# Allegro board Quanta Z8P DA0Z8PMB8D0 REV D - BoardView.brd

Outline 239.8 x 141.8 mm; copper layers: TOP, SGND, IN1, SVCC, IN2, IN3, SGND1, BOTTOM. Coordinates in mm from the lower left corner of the outline.
Outline path: 0,22.1 0.5,24.1 0.5,34.1 arc(0.79,34.81) 1.5,35.1 3,35.1 3,40.05 arc(3.15,40.4) 3.5,40.55 12.03,40.55 arc(12.43,40.15) 12.83,40.55 13.13,40.55 13.13,54.05 12.83,54.05 arc(12.43,54.45) 12.03,54.05 1,54.05 arc(0.65,54.2) 0.5,54.55 0.5,59.11 arc(0.65,59.46) 1,59.61 9.6,59.61 arc(10.09,60.01) 9.8,60.57 9.8,74.05 arc(10.09,74.61) 9.6,75.01 1,75.01 arc(0.65,75.16) 0.5,75.51 0.5,77 arc(0.65,77.35) 1,77.5 2.33,77.5 arc(2.68,77.65) 2.83,78 2.83,79.8 arc(2.68,80.15) 2.33,80.3 1,80.3 arc(0.65,80.45) 0.5,80.8 0.5,90.2 arc(0.65,90.55) 1,90.7 1.76,90.7 arc(2.11,90.85) 2.26,91.2 2.26,92.4 arc(2.11,92.75) 1.76,92.9 1.5,92.9 arc(1.15,93.05) 1,93.4 1,94.04 arc(1.15,94.39) 1.5,94.54 5.6,94.54 arc(5.74,94.48) 5.8,94.34 5.8,93.54 arc(5.86,93.4) 6,93.34 7.8,93.34 arc(7.94,93.4) 8,93.54 8,94.34 arc(8.06,94.48) 8.2,94.54 12.2,94.54 arc(12.34,94.6) 12.4,94.74 12.4,108.74 arc(12.34,108.88) 12.2,108.94 8.2,108.94 arc(8.06,109) 8,109.14 8,109.94 arc(7.94,110.08) 7.8,110.14 6,110.14 arc(5.86,110.08) 5.8,109.94 5.8,109.14 arc(5.74,109) 5.6,108.94 2,108.94 1,109.94 1,111.5 arc(1.07,111.75) 1.25,111.93 2.13,112.44 14.1,112.44 15.5,111.74 15.5,111.5 32.2,111.5 32.2,112.5 arc(32.64,113.56) 33.7,114 34.7,114 arc(35.76,113.56) 36.2,112.5 36.2,111.5 40.7,111.5 48.2,119 48.2,140.8 arc(48.49,141.51) 49.2,141.8 104.7,141.8 arc(105.41,141.51) 105.7,140.8 105.7,138.2 115.7,138.2 115.7,140.8 arc(115.99,141.51) 116.7,141.8 133.7,141.8 arc(134.41,141.51) 134.7,140.8 134.71,96.8 arc(135,96.09) 135.71,95.8 150.71,95.8 arc(151.42,95.51) 151.71,94.8 151.71,54.64 arc(152.01,53.93) 152.71,53.64 164.43,53.64 arc(165.07,53.41) 165.42,52.83 arc(169.28,48.64) 174.74,50.24 arc(177.14,51.53) 179.8,50.99 arc(179.95,50.9) 180.1,50.81 180.09,50.81 arc(180.55,50.22) 180.46,49.47 178.75,46.37 arc(182.83,44.47) 187.09,42.99 202.98,43 217.26,48.19 arc(217.64,48.18) 217.9,47.9 218.2,47.06 218.2,45.5 arc(218.35,45.15) 218.7,45 arc(219.05,44.85) 219.2,44.5 219.2,43.5 arc(219.35,43.15) 219.7,43 220.2,43 arc(220.91,43.29) 221.2,44 221.2,45.4 arc(221.05,45.75) 220.7,45.9 220.1,45.9 arc(219.75,46.05) 219.6,46.4 219.6,48 arc(219.89,48.71) 220.6,49 236.96,49 arc(237.17,48.96) 237.34,48.83 arc(237.86,48.35) 238.49,48.01 arc(238.71,47.83) 238.8,47.55 238.8,42.06 arc(238.95,41.71) 239.3,41.56 arc(239.65,41.42) 239.8,41.06 239.8,33.79 arc(239.51,33.09) 238.8,32.79 236.2,32.8 arc(235.49,32.51) 235.2,31.8 235.2,9.2 arc(234.91,8.49) 234.2,8.2 227.1,8.2 arc(226.39,8.49) 226.1,9.2 226.1,10.3 151.7,10.3 arc(150.99,10.59) 150.7,11.3 150.7,12.3 arc(150.41,13.01) 149.7,13.3 86.9,13.3 86.9,11.3 arc(86.61,10.59) 85.9,10.3 27.5,10.3 14.19,0 12.45,0 arc(11.2,2.6) 9.95,0 3.73,0 arc(3.38,0.15) 3.23,0.5 3.23,4.8 arc(3.08,5.15) 2.73,5.3 1,5.3 arc(0.65,5.45) 0.5,5.8 0.5,14.1 0,16.1 0,22.1

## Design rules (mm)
net group W5-T13B: nets EDP_RCOMP_N EDP_RCOMP_P
net group W5-TB: nets ASM_XIN ASM_XOUT
net group W10-T13B: nets INT_AMIC-VREFO MIC2-VREFO
net group W15-T13B: nets MEM_CH0_RCOMP MEM_CH1_RCOMP
net group W60-T123B: nets LCDVCC LCDVCC_R
net group DFP-S4W4.5(4: nets M_A_CLK0 M_A_CLK0# M_A_DQS0 M_A_DQS1 M_A_DQS2 M_A_DQS3 M_A_DQS4 M_A_DQS5 M_A_DQS6 M_A_DQS7 M_A_DQS#0 M_A_DQS#1 M_A_DQS#2 M_A_DQS#3 M_A_DQS#4 M_A_DQS#5 M_A_DQS#6 M_A_DQS#7 M_B_CLK0 M_B_CLK0# M_B_DQS0 M_B_DQS1 M_B_DQS2 M_B_DQS3 M_B_DQS4 M_B_DQS5 M_B_DQS6 M_B_DQS7 M_B_DQS#0 M_B_DQS#1 M_B_DQS#2 M_B_DQS#3 M_B_DQS#4 M_B_DQS#5 M_B_DQS#6 M_B_DQS#7
net group DFP-S5(4: nets CLK_PCIE_LANN CLK_PCIE_LANP CLK_PCIE_SSDN CLK_PCIE_SSDP CLK_PCIE_WLANN CLK_PCIE_WLANP EDP_AUXN EDP_AUXN_C EDP_AUXP EDP_AUXP_C EDP_TXN0 EDP_TXN0_C EDP_TXN1 EDP_TXN1_C EDP_TXN2 EDP_TXN2_C EDP_TXN3 EDP_TXN3_C EDP_TXP0 EDP_TXP0_C EDP_TXP1 EDP_TXP1_C EDP_TXP2 EDP_TXP2_C EDP_TXP3 EDP_TXP3_C INT_HDMICLK+ INT_HDMICLK+_C INT_HDMICLK+_C_RIN INT_HDMICLK+_C_ROUT INT_HDMICLK+_NOR INT_HDMICLK- INT_HDMICLK-_C INT_HDMICLK-_C_RIN INT_HDMICLK-_C_ROUT INT_HDMICLK-_NOR INT_HDMITX0N INT_HDMITX0N_C INT_HDMITX0N_C_RIN INT_HDMITX0N_C_ROUT INT_HDMITX0N_NOR INT_HDMITX0P INT_HDMITX0P_C INT_HDMITX0P_C_RIN INT_HDMITX0P_C_ROUT INT_HDMITX0P_NOR INT_HDMITX1N INT_HDMITX1N_C_RIN INT_HDMITX1N_C_ROUT INT_HDMITX1N_NOR INT_HDMITX1P INT_HDMITX1P_C_RIN INT_HDMITX1P_C_ROUT INT_HDMITX1P_NOR INT_HDMITX2N INT_HDMITX2N_C_RIN INT_HDMITX2N_C_ROUT INT_HDMITX2N_NOR INT_HDMITX2P INT_HDMITX2P_C INT_HDMITX2P_C_RIN INT_HDMITX2P_C_ROUT INT_HDMITX2P_NOR PCIE_RCOMPN PCIE_RCOMPP PCIE_RX0+_SSD PCIE_RX0-_SSD PCIE_RX1+_SSD PCIE_RX1-_SSD PCIE_RX2+_LAN PCIE_RX2+_LAN_C PCIE_RX2-_LAN PCIE_RX2-_LAN_C PCIE_RX3+_WLAN PCIE_RX3-_WLAN PCIE_TX0+_SSD PCIE_TX0-_SSD PCIE_TX1+_SSD PCIE_TX1-_SSD PCIE_TX2+ PCIE_TX2+_LAN PCIE_TX2- PCIE_TX2-_LAN PCIE_TX3+ PCIE_TX3+_WLAN PCIE_TX3- PCIE_TX3-_WLAN SATA_RXN0 SATA_RXN0_C SATA_RXN0_CN SATA_RXN0_M2 SATA_RXN0_RD SATA_RXN1 SATA_RXN1_R SATA_RXP0 SATA_RXP0_C SATA_RXP0_CN SATA_RXP0_M2 SATA_RXP0_RD SATA_RXP1 SATA_RXP1_R SATA_TXN0 SATA_TXN0_C SATA_TXN0_CN SATA_TXN0_M2 SATA_TXN0_RD SATA_TXN1 SATA_TXN1_C SATA_TXP0 SATA_TXP0_C SATA_TXP0_CN SATA_TXP0_M2 SATA_TXP0_RD SATA_TXP1 SATA_TXP1_C USB3_0_RXN USB3_0_RXN_R USB3_0_RXP USB3_0_RXP_R USB3_0_TXN USB3_0_TXN_C USB3_0_TXN_R USB3_0_TXP USB3_0_TXP_C USB3_0_TXP_R USB3_1_RXN USB3_1_RXP USB3_1_TXN USB3_1_TXN_CN USB3_1_TXP USB3_1_TXP_CN USB3_2_RXN USB3_2_RXP USB3_2_TXN USB3_2_TXN_CN USB3_2_TXP USB3_2_TXP_CN USBP0+ USBP0+_R USBP0- USBP0-_R USBP1+ USBP1- USBP2+ USBP2+_R USBP2- USBP2-_R USBP3+ USBP3+_R USBP3- USBP3-_R USBP4+ USBP4- USBP5+ USBP5- USBP6+ USBP6- USBP7+ USBP7-
net group DFP-S5W5-B: nets PCIE_RX1+_SSD_R PCIE_RX1-_SSD_R PCIE_TX1+_SSD_C PCIE_TX1-_SSD_C
net group DFP-S6.5(7)W5(4: nets ODD_RXN ODD_RXN_C ODD_RXP ODD_RXP_C ODD_TXN ODD_TXN_C ODD_TXP ODD_TXP_C
net group DFP-S20W5(4: nets LAN_MX0+ LAN_MX0- LAN_MX1+ LAN_MX1- LAN_MX2+ LAN_MX2- LAN_MX3+ LAN_MX3- MDI_0+ MDI_0- MDI_1+ MDI_1- MDI_2+ MDI_2- MDI_3+ MDI_3-
net group W5(4: nets 2ND_MBCLK 2ND_MBDATA AZ_CODEC_BITCLK AZ_CODEC_RST# AZ_CODEC_SDIN0 AZ_CODEC_SDOUT AZ_CODEC_SYNC AZ_SDIN0_R CLK_LAN_REQ# CLK_PCI_EC CLK_PCIE_LAN_REQ# CLK_PCIE_SSD_REQ# CLK_SCLK CLK_SDATA CLKDRV_RCOMP CLKREQ_SSD# DDCCLK_NOR DDCCLK_NOR-1 DDCCLK_RIN DDCCLK_ROUT DDCDATA_NOR DDCDATA_NOR-1 DDCDATA_RIN DDCDATA_ROUT DDI0_RCOMP_N DDI0_RCOMP_P DMIC_CLK DMIC_DAT EMMC_CLK EMMC_CMD EMMC_DATA_0 EMMC_DATA_1 EMMC_DATA_2 EMMC_DATA_3 EMMC_DATA_4 EMMC_DATA_5 EMMC_DATA_6 EMMC_DATA_7 EMMC_RCLK FAN_PWM H_CPU_SVIDCLK H_CPU_SVIDDAT HDA_BCLK_R HDA_RST#_R HDA_SDO_R HDA_SYNC_R HDMI_DDCCLK HDMI_DDCCLK_SW HDMI_DDCDATA HDMI_DDCDATA_SW HDMI_HPD HDMI_HPD_NOR HDMI_HPD_NOR-1 HDMI_HPD_RIN HDMI_HPD_RIN_Q HDMI_HPD_ROUT I2C4_SCL I2C4_SCL_C I2C4_SDA I2C4_SDA_C INT_HDMI_HPD# LPC_CLKOUT0 LPC_CLKOUT1 M_A_DQ0 M_A_DQ1 M_A_DQ2 M_A_DQ3 M_A_DQ4 M_A_DQ5 M_A_DQ6 M_A_DQ7 M_A_DQ8 M_A_DQ9 M_A_DQ10 M_A_DQ11 M_A_DQ12 M_A_DQ13 M_A_DQ14 M_A_DQ15 M_A_DQ16 M_A_DQ17 M_A_DQ18 M_A_DQ19 M_A_DQ20 M_A_DQ21 M_A_DQ22 M_A_DQ23 M_A_DQ24 M_A_DQ25 M_A_DQ26 M_A_DQ27 M_A_DQ28 M_A_DQ29 M_A_DQ30 M_A_DQ31 M_A_DQ32 M_A_DQ33 M_A_DQ34 M_A_DQ35 M_A_DQ36 M_A_DQ37 M_A_DQ38 M_A_DQ39 M_A_DQ40 M_A_DQ41 M_A_DQ42 M_A_DQ43 M_A_DQ44 M_A_DQ45 M_A_DQ46 M_A_DQ47 M_A_DQ48 M_A_DQ49 M_A_DQ50 M_A_DQ51 M_A_DQ52 M_A_DQ53 M_A_DQ54 M_A_DQ55 M_A_DQ56 M_A_DQ57 M_A_DQ58 M_A_DQ59 M_A_DQ60 M_A_DQ61 M_A_DQ62 M_A_DQ63 M_B_DQ0 M_B_DQ1 M_B_DQ2 M_B_DQ3 M_B_DQ4 M_B_DQ5 M_B_DQ6 M_B_DQ7 M_B_DQ8 M_B_DQ9 M_B_DQ10 M_B_DQ11 M_B_DQ12 M_B_DQ13 M_B_DQ14 M_B_DQ15 M_B_DQ16 M_B_DQ17 M_B_DQ18 M_B_DQ19 M_B_DQ20 M_B_DQ21 M_B_DQ22 M_B_DQ23 M_B_DQ24 M_B_DQ25 M_B_DQ26 M_B_DQ27 M_B_DQ28 M_B_DQ29 M_B_DQ30 M_B_DQ31 M_B_DQ32 M_B_DQ33 M_B_DQ34 M_B_DQ35 M_B_DQ36 M_B_DQ37 M_B_DQ38 M_B_DQ39 M_B_DQ40 M_B_DQ41 M_B_DQ42 M_B_DQ43 M_B_DQ44 M_B_DQ45 M_B_DQ46 M_B_DQ47 M_B_DQ48 M_B_DQ49 M_B_DQ50 M_B_DQ51 M_B_DQ52 M_B_DQ53 M_B_DQ54 M_B_DQ55 M_B_DQ56 M_B_DQ57 M_B_DQ58 M_B_DQ59 M_B_DQ60 M_B_DQ61 M_B_DQ62 M_B_DQ63 MA_DRAMRST# MB_DRAMRST# MBCLK MBDATA MCSI_DPHY1.1_RCOMP MCSI_DPHY1.2_RCOMP MDSI_RCOMP N22234733 PCH_MBCLK0_R PCH_MBDAT0_R PCH_SPI_CLK PCH_SPI_CS0# PCH_SPI_IO2 PCH_SPI_IO3 PCH_SPI_SI PCH_SPI_SO PCIE_CLKREQ_WLAN# PCLK_TPM PMU_RCOMP RSMRST# RTC_RST# RTC_TEST# RTC_X1 RTC_X2 SD_CLK_R SP1=SD_D1 SP2=SD_D0=MS_D1 SP3=SD_CLK=MS_D0 SP4=SD_CMD=MS_D2 SP5=SD_D3=MS_D3 SP6=SD_D2=MS_CLK SP7=SD_WP=MS_BS SP8=SD_CD# SPI_CLK SPI_CS0 SPI_DI SPI_DO TPCLK TPDATA USB_SSIC_RCOMP USBCOMP VCCGI_SENSE VCCGISS_SENSE VR_SVID_ALERT#_VCORE XTAL192_IN XTAL192_OUT
net group W5(4: nets CLK_PCI_LPC CLKRUN# CLKRUN#_R LPC_LAD0 LPC_LAD0_R LPC_LAD1 LPC_LAD1_R LPC_LAD2 LPC_LAD2_R LPC_LAD3 LPC_LAD3_R LPC_LFRAME# LPC_LFRAME#_R SOC_SERIRQ SOC_SERIRQ_R
net group W6(5: nets M_A_A0 M_A_A1 M_A_A2 M_A_A3 M_A_A4 M_A_A5 M_A_A6 M_A_A7 M_A_A8 M_A_A9 M_A_A10 M_A_A11 M_A_A12 M_A_A13 M_A_A14 M_A_A15 M_A_BS#0 M_A_BS#1 M_A_BS#2 M_A_CAS# M_A_CKE0 M_A_CS#0 M_A_ODT0 M_A_RAS# M_A_WE# M_B_A0 M_B_A1 M_B_A2 M_B_A3 M_B_A4 M_B_A5 M_B_A6 M_B_A7 M_B_A8 M_B_A9 M_B_A10 M_B_A11 M_B_A12 M_B_A13 M_B_A14 M_B_A15 M_B_BS#0 M_B_BS#1 M_B_BS#2 M_B_CAS# M_B_CKE0 M_B_CS#0 M_B_ODT0 M_B_RAS# M_B_WE#
net group W10-T123B: nets +3V_LDO_EC RSET VDD33/18
net group W12-T123B: nets +3V_EC +3VPCU_EC +3VPCU_ECPLL +A3VPCU VSTBY_FSPI
net group W15-T123B: nets +SMDDR_VREF_CA_A +SMDDR_VREF_CA_B +SMDDR_VREF_DQ_A +SMDDR_VREF_DQ_B
net group W20-T13B: nets EMMC_RCOMP GPIO_RCOMP HP-L2 HP-L3 HP-R2 HP-R3 LINE1-L LINE1-R LINE1-VREFO-L LINE1-VREFO-R
net group W20-T123B: nets 1.8V_LDO +1.2V_ASM +1.05V +1.5V +1.5VA +1.8V +1.8V_EMMC +1.8V_S5 +1.24V_S5 +1.35VSUS +3V +3V_ASM +3V_EMMC +3V_M2 +3V_RTC +3V_RTC_1 +3V_S5 +3VPCU +5V +5V_ODD +5V_S5 +5VA +5VPCU +VCC_1.05V_INT +VCC_1.05V_IO +VCC_1.8V +VCC_1.24V_AUD_ISH_PLL +VCC_1.24V_DSI_CSI +VCC_1.24V_GLM +VCC_1.24V_MPHY +VCC_1.24V_USB2 +VCC_3.3V +VDDI_EMMC +VDDQ CODEC_VREF DUALDMIC_PWR HDMI_5V VCCRTC_2
net group W30-T123B: nets +5V_FAN1 LAN_MCT0 LAN_MCT1 LAN_MCT2 LAN_MCT3 TERM9
net group W40-T13B: nets L_SPK+ L_SPK- R_SPK+ R_SPK- RING2 SLEEVE
net group W40-T123B: nets +5V_PVDD +AZA_VDD +VDDQ_VTT +WL_VDD LANVCC REGOUT VCC_XD VDD10 VOUT_BACKLIGHT
net group W50-T123B: nets +TPVDD
net group W80-T123B: nets +TYPEC_VBUS HDD+M2_PWR USBPWR1 USBPWR2

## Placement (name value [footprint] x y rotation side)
C1  180p/50V_4  [C0402]  62.6 132.29 270 top
C2  0.1u/25V_4  [C0402]  60.59 129.42 270 top
C3  330u/2V_7343H1.9  [CC7343]  95.74 123.65 90 top
C4  47u/6.3V_8  [C0805]  107.56 119.46 0 top
C5  0.1u/16V_4  [C0402]  72.28 118.29 180 top
C6  22u/6.3V_6  [C0603]  107.43 117.56 0 top
C7  22u/6.3V_6  [C0603]  88.51 117.43 180 top
C8  22u/6.3V_6  [C0603]  107.43 115.91 0 top
C9  100p/50V_4  [C0402]  52.18 109.43 90 top
C10  0.01u/50V_4  [C0402]  37.09 100.63 0 top
C11  1u/6.3V_4  [C0402]  88.47 97.59 270 top
C12  1u/6.3V_4  [C0402]  81.94 96.99 270 top
C13  1u/6.3V_4  [C0402]  91.36 96.87 270 top
C14  1u/6.3V_4  [C0402]  83.82 96.27 270 top
C15  1u/6.3V_4  [C0402]  90.25 95.77 90 top
C16  1u/6.3V_4  [C0402]  84.44 94.52 90 top
C17  1u/6.3V_4  [C0402]  97.54 94 180 top
C19  1u/6.3V_4  [C0402]  95.24 93.74 270 top
C20  1u/6.3V_4  [C0402]  96.2 93.74 270 top
C21  1u/6.3V_4  [C0402]  97.54 93.04 180 top
C23  1u/6.3V_4  [C0402]  82.77 92.79 270 top
C24  1u/6.3V_4  [C0402]  83.79 92.79 270 top
C25  1u/6.3V_4  [C0402]  93.3 92.58 270 top
C26  1u/6.3V_4  [C0402]  94.26 92.58 270 top
C27  1u/6.3V_4  [C0402]  89.24 91.62 0 top
C28  TPC@0.1u/16V_4  [C0402]  13.85 91.6 0 top
C29  1u/6.3V_4  [C0402]  82.46 91.45 0 top
C30  1u/6.3V_4  [C0402]  96 91.36 270 top
C31  1u/6.3V_4  [C0402]  91.03 91.2 270 top
C32  22u/6.3V_6  [C0603]  94.16 90.86 180 top
C33  22u/6.3V_6  [C0603]  87.01 90.79 180 top
C34  15p/50V_4  [C0402]  67.93 90.66 90 top
C35  22u/6.3V_6  [C0603]  97.91 90.65 0 top
C36  TPC@0.1u/16V_4  [C0402]  13.85 90.58 0 top
C37  1u/6.3V_4  [C0402]  84.26 90.5 270 top
C38  1u/6.3V_4  [C0402]  85.22 90.5 270 top
C39  1u/6.3V_4  [C0402]  82.44 90.48 0 top
C40  22u/6.3V_6  [C0603]  119.58 90.34 270 top
C41  22u/6.3V_6  [C0603]  89.04 89.83 270 top
C42  TPC@10u/6.3V_4  [C0402_2]  22.13 89.27 270 top
C43  TPC@1000p/50V_4  [C0402]  23.32 89.27 270 top
C44  1u/6.3V_4  [C0402]  97.06 89.08 180 top
C45  1u/6.3V_4  [C0402]  83.26 89.04 180 top
C46  22u/6.3V_6  [C0603]  92.13 88.96 270 top
C47  15p/50V_4  [C0402]  67.93 88.88 270 top
C48  1u/6.3V_4  [C0402]  86.12 88.67 180 top
C49  1u/6.3V_4  [C0402]  95.11 88.55 0 top
C50  0.1u/16V_4  [C0402]  76.45 88.51 0 top
C51  TPC@0.1u/16V_4  [C0402]  14.06 88.33 0 top
C52  TPC@10u/6.3V_4  [C0402_2]  31.48 88.09 270 top
C53  TPC@10u/6.3V_4  [C0402_2]  32.88 88.09 270 top
C54  TPC@100p/50V_4  [C0402]  24.6 88.02 270 top
C55  TPC@0.1u/16V_4  [C0402]  14.06 87.31 0 top
C56  1u/6.3V_4  [C0402]  93.7 87.3 0 top
C57  *1u/6.3V_4  [C0402]  95.99 87.23 0 top
C58  0.1u/16V_4  [C0402]  71.61 87.08 0 top
C59  1u/6.3V_4  [C0402]  81.14 86.97 90 top
C60  *1u/6.3V_4  [C0402]  97.35 86.87 90 top
C61  1u/6.3V_4  [C0402]  82.11 86.74 90 top
C62  1u/6.3V_4  [C0402]  83.07 86.74 90 top
C63  1u/6.3V_4  [C0402]  84.03 86.74 90 top
C64  22u/6.3V_6  [C0603]  85.22 86.41 90 top
C65  22u/6.3V_6  [C0603]  86.63 86.41 90 top
C66  22u/6.3V_6  [C0603]  92.13 86.34 270 top
C67  1u/6.3V_4  [C0402]  96.01 86.27 180 top
C68  22u/6.3V_6  [C0603]  123.69 86.25 270 top
C69  *22u/6.3V_6  [C0603]  125.12 86.25 270 top
C70  0.1u/16V_4  [C0402]  76.08 86.1 90 top
C71  1u/6.3V_4  [C0402]  93.63 85.96 90 top
C72  1u/6.3V_4  [C0402]  94.65 85.96 270 top
C73  1u/6.3V_4  [C0402]  88.59 85.85 180 top
C74  1u/6.3V_4  [C0402]  96.28 85.08 180 top
C75  TPC@0.1u/25V_4  [C0402]  13.96 85.81 180 top
C76  1u/6.3V_4  [C0402]  88.59 84.89 180 top
C77  1u/6.3V_4  [C0402]  93.25 84.32 180 top
C78  1u/6.3V_4  [C0402]  87.25 84.2 90 top
C79  0.1u/16V_4  [C0402]  77.14 84.03 0 top
C80  1u/6.3V_4  [C0402]  94.63 83.78 90 top
C81  22u/6.3V_6  [C0603]  90.97 83.58 270 top
C82  1u/6.3V_4  [C0402]  89.65 83.55 90 top
C83  1u/6.3V_4  [C0402]  95.99 83.55 180 top
C84  22u/6.3V_6  [C0603]  97.85 83.53 90 top
C85  22u/6.3V_6  [C0603]  85.11 83.46 0 top
C86  1u/6.3V_4  [C0402]  92.55 83.36 180 top
C87  22u/6.3V_6  [C0603]  82.48 83.02 180 top
C88  22u/6.3V_6  [C0603]  99.87 82.89 0 top
C89  22u/6.3V_6  [C0603]  87.86 82.63 0 top
C90  1u/6.3V_4  [C0402]  93.93 82.36 180 top
C91  22u/6.3V_6  [C0603]  65.75 82.34 270 top
C92  22u/6.3V_6  [C0603]  63.48 82.32 180 top
C93  1u/6.3V_4  [C0402]  92.22 81.51 90 top
C94  22u/6.3V_6  [C0603]  99.16 81.27 0 top
C95  22u/6.3V_6  [C0603]  82.47 80.35 180 top
C96  1u/6.3V_4  [C0402]  94.15 79.19 0 top
C97  0.1u/16V_4  [C0402]  90.25 78.72 90 top
C98  22u/6.3V_6  [C0603]  85.99 78.35 0 top
C99  22u/6.3V_6  [C0603]  94.98 77.61 180 top
C100  22u/6.3V_6  [C0603]  99.88 76.79 0 top
C101  0.1u/16V_4  [C0402]  91.66 76.25 180 top
C102  0.1u/16V_4  [C0402]  88.59 75.69 90 top
C103  0.1u/16V_4  [C0402]  89.93 75.66 180 top
C104  1u/6.3V_4  [C0402]  101.68 75.59 180 top
C105  *0.1u/16V_4  [C0402]  31.6 72.41 180 top
C106  *0.1u/16V_4  [C0402]  31.6 71.4 180 top
C107  *0.1u/16V_4  [C0402]  34.88 70.38 0 top
C108  0.1u/16V_4  [C0402]  37.25 70.38 180 top
C109  *0.1u/16V_4  [C0402]  25.54 70.18 270 top
C110  *0.1u/16V_4  [C0402]  34.88 69.42 0 top
C111  0.1u/16V_4  [C0402]  37.25 69.42 180 top
C112  *0.1u/16V_4  [C0402]  34.88 67.32 0 top
C113  0.1u/16V_4  [C0402]  37.25 67.32 180 top
C114  *0.1u/16V_4  [C0402]  34.88 66.36 0 top
C115  0.1u/16V_4  [C0402]  37.25 66.36 180 top
C116  *0.1u/16V_4  [C0402]  34.88 64.26 0 top
C117  0.1u/16V_4  [C0402]  37.25 64.26 180 top
C118  *0.1u/16V_4  [C0402]  34.88 63.3 0 top
C119  0.1u/16V_4  [C0402]  37.25 63.3 180 top
C120  10u/6.3V_4  [C0402]  54.29 62.03 90 top
C121  1u/6.3V_4  [C0402]  55.36 62.03 270 top
C122  *0.1u/16V_4  [C0402]  34.88 61.19 0 top
C123  0.1u/16V_4  [C0402]  37.25 61.19 180 top
C124  *0.1u/16V_4  [C0402]  34.88 60.23 0 top
C125  0.1u/16V_4  [C0402]  37.25 60.23 180 top
C126  *0.1u/16V_4  [C0402]  27.42 59.77 270 top
C127  *0.1u/16V_4  [C0402]  28.56 59.77 270 top
C128  *0.1u/16V_4  [C0402]  15.48 58.88 180 top
C129  *0.1u/16V_4  [C0402]  30.32 58.83 270 top
C130  *0.1u/16V_4  [C0402]  31.28 58.83 270 top
C131  *0.1u/16V_4  [C0402]  32.24 58.83 270 top
C132  10u/6.3V_4  [C0402]  85.84 58.83 270 top
C133  10u/6.3V_4  [C0402]  64.91 58.53 270 top
C134  10u/6.3V_4  [C0402]  65.92 58.53 270 top
C135  1u/6.3V_4  [C0402]  23.74 58.23 0 top
C136  1u/6.3V_4  [C0402]  118.05 58.2 270 top
C137  *0.1u/16V_4  [C0402]  15.48 57.87 180 top
C138  4.7u/6.3V_4  [C0402_2]  12.77 57.75 270 top
C139  470p/50V_4  [C0402]  47.87 57.61 180 top
C140  470p/50V_4  [C0402]  50.41 57.61 180 top
C141  0.1u/16V_4  [C0402]  47.87 56.6 0 top
C142  0.1u/16V_4  [C0402]  50.41 56.6 0 top
C143  1u/6.3V_4  [C0402]  85.84 56.55 270 top
C144  0.1u/16V_4  [C0402]  20.07 55.62 90 top
C145  470p/50V_4  [C0402]  21.03 55.62 90 top
C146  2.2u/10V_4  [C0402]  47.87 55.58 0 top
C147  2.2u/10V_4  [C0402]  50.41 55.58 0 top
C148  1u/6.3V_4  [C0402]  68.58 55.02 90 top
C149  470p/50V_4  [C0402]  118.35 54.56 0 top
C150  10u/6.3V_4  [C0402]  103.16 54.33 270 top
C151  10u/6.3V_4  [C0402]  100.95 54.17 0 top
C152  0.1u/16V_4  [C0402]  118.35 53.55 180 top
C153  1u/6.3V_4  [C0402]  68.58 53.16 270 top
C154  0.1u/16V_4  [C0402]  25.2 52.91 0 top
C155  *1.6p/50V_4  [C0402]  20.55 52.79 0 top
C156  2.2u/10V_4  [C0402]  118.35 52.53 180 top
C157  1u/6.3V_4  [C0402]  82.66 52.41 90 top
C158  10u/6.3V_4  [C0402]  85.84 52.41 270 top
C159  0.1u/16V_4  [C0402]  25.2 51.95 0 top
C160  10u/6.3V_4  [C0402]  50.66 51.67 90 top
C161  *1.6p/50V_4  [C0402]  20.55 51.52 0 top
C162  10u/6.3V_4  [C0402]  50.61 49.61 270 top
C163  2.2u/10V_4  [C0402]  118.35 49.23 180 top
C164  10u/6.3V_4  [C0402]  85.41 48.8 180 top
C165  0.1u/16V_4  [C0402]  118.35 48.21 180 top
C166  1u/6.3V_4  [C0402]  82.82 47.88 270 top
C167  470p/50V_4  [C0402]  118.35 47.2 0 top
C168  1u/6.3V_4  [C0402]  82.82 45.93 90 top
C169  *1.6p/50V_4  [C0402]  30.6 45.5 0 top
C170  *1.6p/50V_4  [C0402]  30.61 44.3 0 top
C171  1u/6.3V_4  [C0402]  118.35 44.07 180 top
C172  10u/6.3V_4  [C0402_2]  159.75 43.39 0 top
C173  0.1u/16V_4  [C0402]  159.75 42.25 180 top
C174  0.1u/16V_4  [C0402]  159.75 41.23 180 top
C175  1u/6.3V_4  [C0402]  118.38 42.98 180 top
C176  0.1u/16V_4  [C0402]  23.4 40.99 90 top
C177  0.1u/16V_4  [C0402]  25.32 41.24 90 top
C178  0.1u/16V_4  [C0402]  33.56 40.8 90 top
C179  10p/50V_4  [C0402]  26.96 40.62 180 top
C180  10p/50V_4  [C0402]  28.87 40.62 0 top
C181  EJ@0.01u/50V_4  [C0402]  209.73 40.14 180 top
C182  0.1u/16V_4  [C0402]  201.4 40.08 180 top
C183  0.01u/50V_4  [C0402]  201.4 39.06 180 top
C184  EJ@0.01u/50V_4  [C0402]  209.73 38.61 180 top
C185  0.01u/50V_4  [C0402]  201.42 38.05 180 top
C186  0.1u/16V_4  [C0402]  34.61 38.04 90 top
C187  *0.1u/16V_4  [C0402]  35.57 38.04 90 top
C188  10u/6.3V_4  [C0402_2]  36.64 38.04 270 top
C189  0.1u/16V_4  [C0402]  22.7 37.45 180 top
C190  TPM@10u/6.3V_4  [C0402_2]  153.02 37.26 180 top
C191  EJ@0.01u/50V_4  [C0402]  209.73 37.08 180 top
C192  CB@0.01u/50V_4  [C0402]  210.52 37.08 0 top
C193  0.01u/50V_4  [C0402]  201.42 37.03 180 top
C194  180p/50V_4  [C0402]  145.53 36.66 270 top
C195  180p/50V_4  [C0402]  135.68 36.18 0 top
C196  TPM@0.1u/16V_4  [C0402]  153.02 36.12 180 top
C197  0.01u/50V_4  [C0402]  201.42 35.93 180 top
C198  CB@0.01u/50V_4  [C0402]  210.56 35.62 0 top
C199  EJ@0.01u/50V_4  [C0402]  209.76 35.62 180 top
C200  4.7u/6.3V_4  [C0402_2]  33.83 35.18 90 top
C201  TPM@0.1u/16V_4  [C0402]  163 35.06 180 top
C202  0.1u/16V_4  [C0402]  35.12 34.89 270 top
C203  0.1u/16V_4  [C0402]  36.08 34.89 270 top
C204  *0.1u/16V_4  [C0402]  37.04 34.89 270 top
C205  0.1u/16V_4  [C0402]  138.26 34.75 270 top
C206  0.1u/16V_4  [C0402]  142.46 34.75 270 top
C207  180p/50V_4  [C0402]  132.05 34.63 270 top
C208  0.1u/16V_4  [C0402]  133.01 34.63 270 top
C209  0.1u/16V_4  [C0402]  135.02 34.63 270 top
C210  0.1u/16V_4  [C0402]  22.23 34.54 180 top
C211  0.1u/16V_4  [C0402]  208.22 33.99 270 top
C212  1000p/50V_4  [C0402]  34.21 33.16 90 top
C213  0.1u/16V_4  [C0402]  198.59 33.13 270 top
C214  0.1u/16V_4  [C0402]  199.55 33.13 270 top
C215  0.1u/16V_4  [C0402]  23.13 32.86 180 top
C216  *EJ@220p/50V_4  [C0402]  211.2 32.69 0 top
C217  TPM@10u/6.3V_4  [C0402_2]  153.02 32.62 0 top
C218  *EJ@220p/50V_4  [C0402]  216.64 32.26 180 top
C219  *1u/6.3V_4  [C0402]  197.57 32.06 270 top
C220  0.1u/16V_4  [C0402]  203.19 31.96 270 top
C221  180p/50V_4  [C0402]  162.86 31.55 270 top
C222  TPM@0.1u/16V_4  [C0402]  153.02 31.45 0 top
C223  10u/6.3V_4  [C0402_2]  207 31.42 0 top
C224  0.1u/16V_4  [C0402]  31.77 31.03 90 top
C225  0.1u/16V_4  [C0402]  32.73 31.03 90 top
C226  *4.7u/6.3V_4  [C0402_2]  33.8 31.03 90 top
C227  0.1u/16V_4  [C0402]  34.87 31.03 270 top
C228  10u/6.3V_4  [C0402_2]  195.54 29.98 270 top
C229  0.1u/16V_4  [C0402]  196.84 30.15 270 top
C230  10u/6.3V_4  [C0402_2]  206.74 29.7 270 top
C231  2.2u/10V_4  [C0402]  207.89 29.7 90 top
C232  *10p/50V_4  [C0402]  18.01 29.62 180 top
C233  TPM@33p/50V_4  [C0402]  157.7 29.29 270 top
C234  TPM@0.1u/16V_4  [C0402]  158.85 29.29 90 top
C235  0.1u/16V_4  [C0402]  231.37 28.77 180 top
C236  0.1u/16V_4  [C0402]  160.81 26.9 180 top
C237  2.2u/10V_4  [C0402]  207.61 28.36 0 top
C238  *10p/50V_4  [C0402]  18.01 27.92 180 top
C239  0.1u/16V_4  [C0402]  231.37 27.81 180 top
C240  0.1u/16V_4  [C0402]  160.81 25.94 180 top
C241  10p/50V_4  [C0402]  193.03 27.34 0 top
C242  *GS@22p/50V_4  [C0402]  163.43 27.23 180 top
C243  100p/50V_4  [C0402]  209.92 27.03 0 top
C244  0.01u/50V_4  [C0402]  231.13 26.83 180 top
C245  *10p/50V_4  [C0402]  196.42 26.61 0 top
C246  10p/50V_4  [C0402]  18.02 26.46 0 top
C247  *22p/50V_4  [C0402]  194.14 26.09 180 top
C248  10u/6.3V_4  [C0402_2]  231.13 25.76 0 top
C249  2.2u/10V_4  [C0402]  207.76 25.74 0 top
C250  10u/6.3V_4  [C0402_2]  196.43 25.51 0 top
C251  0.1u/16V_4  [C0402]  126.97 25.23 180 top
C252  0.1u/16V_4  [C0402]  128.74 25.23 0 top
C253  1u/6.3V_4  [C0402]  188.07 24.85 90 top
C254  1u/6.3V_4  [C0402]  190.49 24.85 90 top
C255  10u/6.3V_4  [C0402_2]  207.76 24.59 0 top
C256  180p/50V_4  [C0402]  150.1 24.52 180 top
C257  0.1u/16V_4  [C0402]  196.43 24.36 0 top
C258  180p/50V_4  [C0402]  155.41 25.89 180 top
C259  0.1u/16V_4  [C0402]  207.76 23.45 180 top
C260  *0.1u/16V_4  [C0402]  212.86 23.4 180 top
C261  10u/6.3V_4  [C0402_2]  196.43 23.12 0 top
C262  4.7u/6.3V_4  [C0402_2]  17.84 22.86 270 top
C263  0.1u/16V_4  [C0402]  19.24 22.86 90 top
C264  0.1u/16V_4  [C0402]  195.92 21.77 0 top
C265  KBL@2.2u/10V_4  [C0402]  230.69 21.34 90 top
C266  0.1u/16V_4  [C0402]  115.79 21.13 270 top
C267  0.1u/16V_4  [C0402]  151.12 20.93 180 top
C268  100p/50V_4  [C0402]  194.14 20.63 180 top
C269  0.1u/16V_4  [C0402]  116.81 19.25 90 top
C270  0.22u/10V_4  [C0402]  117.77 19.25 90 top
C271  *100u/6.3V_12  [C1206]  225.84 18.72 90 top
C272  10u/6.3V_4  [C0402_2]  149.41 17.99 0 top
C273  KBL@4.7u/6.3V_4  [C0402_2]  227.57 17.48 90 top
C274  0.1u/16V_4  [C0402]  222.9 18.37 90 top
C275  470p/50V_4  [C0402]  223.89 18.37 90 top
C276  180p/50V_4  [C0402]  148.73 15.82 270 top
C277  GS@10u/6.3V_4  [C0402_2]  150.79 15.93 270 top
C278  1u/6.3V_4  [C0402]  226.94 14.18 90 top
C279  KBL@0.01u/50V_4  [C0402]  227.95 14.18 270 top
C280  GS@0.1u/16V_4  [C0402]  161.53 13.29 90 top
C281  1000p/50V_4  [C0402]  63.12 126.3 90 bottom
C282  0.1u/16V_4  [C0402]  64.08 126.3 90 bottom
C283  1000p/50V_4  [C0402]  62.73 123.92 270 bottom
C284  0.1u/16V_4  [C0402]  63.69 123.92 270 bottom
C285  0.1u/16V_4  [C0402]  64.83 122.41 0 bottom
C286  0.1u/16V_4  [C0402]  64.83 121.14 0 bottom
C287  0.1u/16V_4  [C0402]  64.83 120.18 0 bottom
C288  0.1u/16V_4  [C0402]  64.83 119.22 0 bottom
C289  0.1u/16V_4  [C0402]  63.11 118.68 0 bottom
C290  0.1u/16V_4  [C0402]  63.11 117.72 0 bottom
C291  0.1u/16V_4  [C0402]  64.83 117.18 0 bottom
C292  47u/6.3V_8  [C0805]  74.41 117.18 180 bottom
C293  47u/6.3V_8  [C0805]  81.14 117.18 0 bottom
C294  0.1u/16V_4  [C0402]  64.83 116.22 0 bottom
C295  0.1u/16V_4  [C0402]  63.11 115.68 0 bottom
C296  47u/6.3V_8  [C0805]  88.51 115.39 180 bottom
C297  47u/6.3V_8  [C0805]  74.41 115.14 180 bottom
C298  47u/6.3V_8  [C0805]  81.14 115.14 0 bottom
C299  0.1u/16V_4  [C0402]  63.11 114.72 0 bottom
C300  47u/6.3V_8  [C0805]  88.51 113.42 180 bottom
C301  47u/6.3V_8  [C0805]  81.14 113.11 0 bottom
C302  47u/6.3V_8  [C0805]  74.41 112.98 180 bottom
C303  22u/6.3V_6  [C0603]  83.55 111.33 0 bottom
C304  47u/6.3V_8  [C0805]  74.41 110.95 180 bottom
C305  22u/6.3V_6  [C0603]  83.55 109.81 0 bottom
C306  0.1u/16V_4  [C0402]  63.19 109.45 180 bottom
C307  EJ@1000p/3KV_1808  [CC1808]  42.91 106.51 0 bottom
C308  0.01u/50V_4  [C0402]  62.16 107.59 0 bottom
C309  15p/50V_4  [C0402]  99.21 106.58 180 bottom
C310  15p/50V_4  [C0402]  100.93 106.58 0 bottom
C311  22u/6.3V_6  [C0603]  61.77 106.4 0 bottom
C312  PSD@0.01u/50V_4  [C0402]  41.92 104.28 180 bottom
C313  1000p/50V_4  [C0402]  106.94 103.71 270 bottom
C314  PSD@0.01u/50V_4  [C0402]  41.92 103.14 180 bottom
C315  1u/6.3V_4  [C0402]  62.02 102.61 90 bottom
C316  EC@0.1u/16V_4  [C0402]  60.6 101.86 0 bottom
C317  EC@1u/6.3V_4  [C0402]  60.6 100.81 180 bottom
C318  *EC@5.6p/50V_4  [C0402]  58.04 100.59 0 bottom
C319  EC@0.1u/16V_4  [C0402]  60.59 99.68 0 bottom
C320  EC@1u/6.3V_4  [C0402]  54.94 99 0 bottom
C321  EC@0.1u/16V_4  [C0402]  60.59 98.67 0 bottom
C322  EC@0.1u/16V_4  [C0402]  54.94 97.98 180 bottom
C323  PSD@0.01u/50V_4  [C0402]  48.16 97.92 270 bottom
C324  PSD@0.01u/50V_4  [C0402]  49.3 97.92 270 bottom
C325  SSD@0.01u/50V_4  [C0402]  48.16 97.15 90 bottom
C326  SSD@0.01u/50V_4  [C0402]  49.3 97.15 90 bottom
C327  EC@0.1u/16V_4  [C0402]  54.9 95.69 270 bottom
C328  EC@1u/6.3V_4  [C0402]  55.91 95.69 90 bottom
C329  EC@0.1u/16V_4  [C0402]  56.93 95.69 270 bottom
C330  EC@0.1u/16V_4  [C0402]  60.8 95.34 270 bottom
C331  EC@1u/6.3V_4  [C0402]  58.64 94.58 180 bottom
C332  0.1u/16V_4  [C0402]  109.07 94.12 180 bottom
C333  0.1u/16V_4  [C0402]  109.07 93.16 180 bottom
C334  0.1u/16V_4  [C0402]  108.72 91.56 180 bottom
C335  0.1u/16V_4  [C0402]  108.72 90.6 180 bottom
C336  *10p/50V_4  [C0402]  69.66 88.11 180 bottom
C337  0.1u/16V_4  [C0402]  25.38 87.49 0 bottom
C338  0.1u/16V_4  [C0402]  21.77 87.42 180 bottom
C339  10u/6.3V_4  [C0402_2]  42.86 86.96 0 bottom
C340  TPC@0.47u/25V_6  [C0603]  13.54 86.85 180 bottom
C341  TPC@0.47u/25V_6  [C0603]  18.77 86.88 0 bottom
C342  TPC@1000p/50V_4  [C0402]  8.29 86.69 270 bottom
C343  TPC@0.1u/25V_4  [C0402]  11.32 86.66 90 bottom
C344  TPC@0.1u/25V_4  [C0402]  16.29 86.32 90 bottom
C345  0.1u/16V_4  [C0402]  25.38 86.14 0 bottom
C346  0.1u/16V_4  [C0402]  42.86 85.89 0 bottom
C347  TPC@0.47u/25V_6  [C0603]  18.77 85.47 0 bottom
C348  22u/6.3V_6  [C0603]  110.21 84.54 180 bottom
C349  TPC@0.47u/25V_6  [C0603]  19.39 83.39 90 bottom
C350  TPC@100p/50V_4  [C0402]  7.63 83.78 270 bottom
C351  22u/6.3V_6  [C0603]  110.97 83.01 180 bottom
C352  CB@0.01u/50V_4  [C0402]  114.45 79.13 0 bottom
C353  *220p/50V_4  [C0402]  15.1 71.33 270 bottom
C354  1u/6.3V_4  [C0402]  54.29 62.03 270 bottom
C355  1u/6.3V_4  [C0402]  85.84 58.83 90 bottom
C356  1u/6.3V_4  [C0402]  50.41 58.65 0 bottom
C357  1u/6.3V_4  [C0402]  64.9 58.53 90 bottom
C358  1u/6.3V_4  [C0402]  118.05 58.2 270 bottom
C359  100u/6.3V_12  [C1206]  18.38 57.94 90 bottom
C360  1u/6.3V_4  [C0402]  85.84 56.55 270 bottom
C361  1u/6.3V_4  [C0402]  50.41 55.58 0 bottom
C362  10u/6.3V_4  [C0402]  118.35 55.58 0 bottom
C363  1u/6.3V_4  [C0402]  103.77 54.46 90 bottom
C364  1u/6.3V_4  [C0402]  101.55 54.31 90 bottom
C365  1u/6.3V_4  [C0402]  68.49 54.26 90 bottom
C366  1u/6.3V_4  [C0402]  118.35 52.53 180 bottom
C367  1u/6.3V_4  [C0402]  82.66 52.41 90 bottom
C368  1u/6.3V_4  [C0402]  85.84 52.41 90 bottom
C369  1u/6.3V_4  [C0402]  50.66 51.67 270 bottom
C370  0.1u/16V_4  [C0402]  18.27 51.26 0 bottom
C371  10u/6.3V_4  [C0402]  82.82 49.74 270 bottom
C372  1u/6.3V_4  [C0402]  85.86 48.01 270 bottom
C373  1u/6.3V_4  [C0402]  82.82 47.88 270 bottom
C374  1u/6.3V_4  [C0402]  50.61 47.81 270 bottom
C375  1u/6.3V_4  [C0402]  118.35 47.22 180 bottom
C376  1u/6.3V_4  [C0402]  118.35 46.23 180 bottom
C377  1u/6.3V_4  [C0402]  82.82 45.93 90 bottom
C378  1u/6.3V_4  [C0402]  85.86 45.9 90 bottom
C379  1u/6.3V_4  [C0402]  50.66 45.52 90 bottom
C380  0.1u/16V_4  [C0402]  133.97 42.25 270 bottom
C381  10u/6.3V_4  [C0402_2]  205.4 39.42 0 bottom
C382  1u/6.3V_4  [C0402]  203.08 39.05 90 bottom
C383  1u/6.3V_4  [C0402]  204.04 39.05 90 bottom
C384  *0.1u/16V_4  [C0402]  143.62 29.93 0 bottom
C385  ODD@0.1u/16V_4  [C0402]  112.37 37.84 180 bottom
C386  0.1u/16V_4  [C0402]  33.77 36.47 0 bottom
C387  ODD@0.1u/16V_4  [C0402]  112.66 36.4 90 bottom
C388  ODD@0.1u/16V_4  [C0402]  113.62 36.4 90 bottom
C389  ODD@0.1u/16V_4  [C0402]  114.58 36.4 90 bottom
C390  ODD@1u/6.3V_4  [C0402]  117.49 36.4 270 bottom
C391  ODD@0.1u/16V_4  [C0402]  118.45 36.4 90 bottom
C392  ODD@0.1u/16V_4  [C0402]  119.41 36.4 90 bottom
C393  1u/6.3V_4  [C0402]  150.09 36.18 0 bottom
C394  TPC@100u/6.3V_12  [C1206]  47.36 36.02 180 bottom
C395  ODD@10p/50V_4  [C0402]  121.97 35.3 0 bottom
C396  2.2u/10V_4  [C0402]  150.09 34.96 180 bottom
C397  1u/6.3V_4  [C0402]  203.34 34.4 90 bottom
C398  ODD@0.1u/16V_4  [C0402]  110.98 34.01 180 bottom
C399  *100u/6.3V_12  [C1206]  223.51 32.82 90 bottom
C400  ODD@0.1u/16V_4  [C0402]  121.78 32.88 180 bottom
C401  10u/6.3V_4  [C0402_2]  203.19 31.96 90 bottom
C402  *0.1u/16V_4  [C0402]  133.46 31.7 90 bottom
C403  1u/6.3V_4  [C0402]  30.22 31.61 180 bottom
C404  ODD@0.1u/16V_4  [C0402]  121.78 31.58 0 bottom
C405  ODD@2.2u/10V_4  [C0402]  109.3 31.43 270 bottom
C406  ODD@0.1u/16V_4  [C0402]  110.98 30.93 180 bottom
C407  0.1u/16V_4  [C0402]  30.22 30.65 0 bottom
C408  0.1u/16V_4  [C0402]  150.17 30.22 180 bottom
C409  0.01u/50V_4  [C0402]  224.06 29.62 270 bottom
C410  0.1u/16V_4  [C0402]  150.17 29.26 180 bottom
C411  10u/6.3V_4  [C0402_2]  200.75 28.88 90 bottom
C412  10u/6.3V_4  [C0402_2]  202.02 28.88 90 bottom
C413  ODD@4.7u/6.3V_4  [C0402_2]  110.98 28.52 180 bottom
C414  ODD@0.1u/16V_4  [C0402]  121.07 28.46 270 bottom
C415  0.1u/16V_4  [C0402]  150.17 28.3 180 bottom
C416  1u/6.3V_4  [C0402]  133.53 27.99 270 bottom
C417  100p/50V_4  [C0402]  209.92 27.03 0 bottom
C418  *ODD@100u/6.3V_12  [C1206]  145.27 25.86 0 bottom
C419  ODD@0.1u/16V_4  [C0402]  118.19 25.75 0 bottom
C420  *10p/50V_4  [C0402]  133.67 25.67 0 bottom
C421  ODD@10u/6.3V_4  [C0402_2]  114.43 25.61 270 bottom
C422  ODD@0.1u/16V_4  [C0402]  120.5 25.35 270 bottom
C423  4.7u/6.3V_4  [C0402_2]  207.76 25.2 180 bottom
C424  ODD@0.01u/50V_4  [C0402]  131.22 24.72 0 bottom
C425  180p/50V_4  [C0402]  133.06 24.71 180 bottom
C426  ODD@1u/6.3V_4  [C0402]  118.58 24.35 270 bottom
C427  ODD@0.01u/50V_4  [C0402]  131.22 23.76 0 bottom
C428  10u/6.3V_4  [C0402_2]  207.76 23.63 180 bottom
C429  ODD@10u/6.3V_4  [C0402_2]  142.76 22.94 0 bottom
C430  ODD@0.01u/50V_4  [C0402]  145.15 22.94 0 bottom
C431  ODD@0.01u/50V_4  [C0402]  131.22 22.8 0 bottom
C432  1000p/50V_4  [C0402]  189.33 22.26 270 bottom
C433  1000p/50V_4  [C0402]  187.81 21.62 270 bottom
C434  1000p/50V_4  [C0402]  190.42 22.26 270 bottom
C435  1000p/50V_4  [C0402]  191.82 22.26 270 bottom
C436  *1000p/50V_4  [C0402]  198.77 22.03 0 bottom
C437  ODD@0.01u/50V_4  [C0402]  131.22 21.84 0 bottom
C438  ODD@0.1u/16V_4  [C0402]  142.76 21.8 180 bottom
C439  ODD@0.01u/50V_4  [C0402]  145.15 21.8 0 bottom
C440  0.1u/16V_4  [C0402]  130.92 20.4 270 bottom
C441  100p/50V_4  [C0402]  200.29 20.86 270 bottom
C442  100p/50V_4  [C0402]  203.52 20.86 270 bottom
C443  10u/6.3V_4  [C0402_2]  204.79 20.86 90 bottom
C444  4.7u/6.3V_4  [C0402_2]  206.11 20.86 90 bottom
C445  *10p/50V_4  [C0402]  14 13.73 0 bottom
C446  *10p/50V_4  [C0402]  12.98 12.65 0 bottom
C447  *10p/50V_4  [C0402]  14.85 11.54 270 bottom
C448  0.1u/16V_4  [C0402]  25.39 30.56 180 top
C449  0.1u/16V_4  [C0402]  139.28 34.37 270 top
CN1  *TPC@AUSB0181-P101A  [UB31-AUSB0181-P101A-24P]  6.6 85.8 270 top
CN2  156-1001902602  [SDCARD-156-1001902602-11P-SMT]  11.1 19.9 270 top
CN3  196538-40041-3  [51540-04001-V01-40P-L]  57.51 120.2 90 bottom
CN4  JMP1H01-R3401-7H  [RJ45-JM361C-HP34AA03-9H-8P-SMT]  3.25 101.74 90 bottom
CN5  NASM0-S6701-TS40  [NGFF-NASM0-S6701-TS40-75P-KM]  31.93 91.7 180 bottom
CN6  HMRBL-AK120C  [HDMI-HMRBL-AK120C-19P]  3 67.31 90 bottom
CN7  CB@cable RTC  [50281-00201-001-2P-L]  160.7 51.9 0 bottom
CN8  2UB4008-390101F  [UB3-53930-00902-V01-9P]  6.12 47.3 90 bottom
CN9  APCI0076-P001A  [NGFF-APCI0076-P001A-75P-KE-SMT]  158.42 35 270 bottom
CN10  EJ@50278-00401-V01  [50278-00401-001-4P-L]  216.04 34.75 120 bottom
CN11  CB@132F10-000000-A2-R  [132F10-000000-A2-R-10P-L]  231.85 28.2 270 bottom
CN12  GS12201-1011-7H  [GS12201-1011-9H-20P-L]  229.07 27.7 270 bottom
CN13  EJ@53014-00201-V09  [ML1220-SMT]  12.31 26.8 270 bottom
CN14  50584-0280N-V02  [50584-0280N-V02-28P-L]  165.9 19.6 180 bottom
CN15  51653-0080N-001  [51653-0080N-V02-8P-L]  112.2 18.32 180 bottom
CN16  ODD@18 pin conn  [51605-01801-001-18P-L]  139.2 16.7 180 bottom
CN17  196332-34041-3  [196332-34041-3-34P-L]  215.6 15.35 180 bottom
CN18  KBL@50591-00401-001  [50591-00401-001-4P-L]  230 14.35 270 bottom
CN19  50278-00401-V01  [50278-00401-001-4P-L]  191.9 13.53 180 bottom
D1  1N4148WS  [DSM]  46.72 109.94 0 top
D2  EC@RB500V-40  [DSM]  54.85 85.68 180 top
D3  TPC@AZ5725-01F.R7G  [ESD-1X0_6-2P]  22.8 78.82 180 top
D4  *AZ5725-01F.R7G  [ESD-1X0_6-2P]  16.5 72.01 270 top
D5  *AZ5725-01F.R7G  [ESD-1X0_6-2P]  16.5 70.14 90 top
D6  VARISTOR  [R0402]  135.68 37.17 180 top
D7  GS@RB500V-40  [DSM]  159.58 22.74 180 top
D8  GS@RB500V-40  [DSM]  159.58 20.96 180 top
D9  *AZ5725-01F.R7G  [ESD-1X0_6-2P]  212.99 21.7 180 top
D10  *AZ5725-01F.R7G  [ESD-1X0_6-2P]  212.99 20.4 180 top
D11  *AZ5725-01F.R7G  [ESD-1X0_6-2P]  63.23 113.74 0 bottom
D12  *AZ5725-01F.R7G  [ESD-1X0_6-2P]  63.23 112.43 0 bottom
D13  *AZ5725-01F.R7G  [ESD-1X0_6-2P]  63.23 111.42 0 bottom
D14  *AZ5725-01F.R7G  [ESD-1X0_6-2P]  64.59 109.73 90 bottom
D15  *RB500V-40  [DSM]  121.4 41.74 270 bottom
D16  *RB500V-40  [DSM]  123.43 41.74 270 bottom
D17  *RB500V-40  [DSM]  125.46 41.74 270 bottom
D18  *RB500V-40  [DSM]  127.49 41.74 270 bottom
D19  *RB500V-40  [DSM]  129.53 41.74 270 bottom
D20  RB500V-40  [DSM]  131.56 41.74 270 bottom
D21  *RB500V-40  [DSM]  198.19 34.46 0 bottom
D22  RB500V-40  [DSM]  195.43 31.27 0 bottom
D23  1N4148WS  [DSM]  195.43 29.32 0 bottom
D24  RB500V-40  [DSM]  131.13 28.77 270 bottom
D25  1N4148WS  [DSM]  195.43 27.4 0 bottom
D26  BAT54CW  [UMT_213-3-1_3]  189.89 27.57 0 bottom
D27  *AZ5725-01F.R7G  [ESD-1X0_6-2P]  113.12 22.87 0 bottom
D28  *AZ5725-01F.R7G  [ESD-1X0_6-2P]  115.16 22.87 180 bottom
D29  *VARISTOR  [R0402]  15.25 73.79 270 bottom
D30  *VARISTOR  [R0402]  16.37 71.33 270 bottom
ESD1  TPC@TVL ST23 04 AD0  [SOT23-6-2_8-95-6P]  17.59 87.81 90 top
ESD2  TPC@AZ1045-08F.R7G  [ESD-3_8X1-9P]  11.54 87.58 270 top
ESD3  AZ1065-06F.R7G  [DFN10-4_1X2-8-11P]  18.08 49.38 270 top
ESD4  *TVL ST23 04 AD0  [SOT23-6-2_8-95-6P]  110.6 19.03 90 top
ESD5  *TVL ST23 04 AD0  [SOT23-6-2_8-95-6P]  215.86 16.58 90 top
ESD6  *AZ1045-04F.R7G  [UDFN10-2_5X1-5-9P]  15.4 67.52 90 bottom
ESD7  *AZ1045-04F.R7G  [UDFN10-2_5X1-5-9P]  15.4 63.2 90 bottom
HOLE1  *H-C236D94P2  [H-C236D94P2]  118.1 138 90 top
HOLE2  *HG-EJ-AP-1  [HG-EJ-AP-1]  54.2 136.7 0 top
HOLE3  CPU nut  [H-TC252IC138BC252D138P2]  125.7 95.4 180 bottom
HOLE4  CPU nut  [H-TC252IC138BC252D138P2]  54.7 80.07 180 bottom
HOLE5  *HG-Z8P-1  [HG-Z8P-1]  12.7 79.8 0 top
HOLE6  *O-EJ-KBL-1  [O-EJ-KBL-1]  77.2 68.75 90 top
HOLE7  CPU nut  [H-TC252IC138BC252D138P2]  137.47 59.52 180 bottom
HOLE8  *HG-C315D165P2  [HG-C315D165P2]  31.93 51.45 90 top
HOLE9  WLAN nut  [H-C236D126P2]  186.67 35 180 bottom
HOLE10  *H-C122D122N  [H-C122D122N]  215.7 44.6 90 top
HOLE11  *HG-C354D220P2  [HG-C354D220P2]  220.2 24.3 0 top
HOLE12  *HG-C354D220P2  [HG-C354D220P2]  125.2 19.1 0 top
HOLE13  *HG-TC315BC236D95P2  [HG-TC315BC236D95P2]  21.2 14.8 90 top
HOLE14  *HG-C315D165P2  [HG-C315D165P2]  31.93 13.45 90 top
HOLE15  *HG-C354D126P2  [HG-C354D126P2]  11.2 1 0 top
J1  *JUMP  [JOPEN25X30_S]  186.13 21.89 270 bottom
JP1  *S_3720  [SHORT3720]  123.18 131.78 90 bottom
JP2  *S_3720  [SHORT3720]  71.49 130.26 180 bottom
JP3  *S_3720  [SHORT3720]  88.43 126.4 180 bottom
JP4  *S_3720  [SHORT3720]  126.61 118.19 90 bottom
JP5  *S_3720  [SHORT3720]  114.16 102.7 90 bottom
JP6  *S_3720  [SHORT3720]  130.29 100.92 0 bottom
JP7  *S_3720  [SHORT3720]  137.65 83.39 90 bottom
JP8  *S_3720  [SHORT3720]  143.88 65.36 180 bottom
JP9  *S_3720  [SHORT3720]  93.15 32.11 90 bottom
JP10  *S_3720  [SHORT3720]  86.6 31.58 0 bottom
JP11  *S_3720  [SHORT3720]  41.9 79.33 270 top
JP12  *S_3720  [SHORT3720]  125.46 82.63 90 bottom
L1  *MCM2012B900GBE  [FILTER-MCM2012B900GBE-4P]  22.85 52.43 0 top
L2  *MCM2012B900GBE  [FILTER-MCM2012B900GBE-4P]  22.83 50.45 0 top
L3  *MCM2012B900GBE  [FILTER-MCM2012B900GBE-4P]  27.76 45.35 0 top
L4  BLM15AG121SN1D  [R0402]  133.01 36.49 270 top
L5  BLM15AG121SN1D  [R0402]  150.1 21.97 180 top
L6  *MCM2012B900GBE  [FILTER-MCM2012B900GBE-4P]  218.61 15.06 90 top
L7  *MCM2012B900GBE  [FILTER-MCM2012B900GBE-4P]  220.58 14.55 90 top
L8  PBY160808T-600Y-N  [R0603]  204.69 33.08 270 bottom
L9  PBY160808T-600Y-N  [R0603]  199.35 28.76 270 bottom
L10  ODD@4.7uH_3.2x2.5x1.55  [L3_2X2_5-1_55]  111.25 25.74 90 bottom
L11  PBY160808T-600Y-N  [R0603]  199.41 23.45 180 bottom
L12  BLM15AG121SN1D  [R0402]  130.92 18.62 90 bottom
NOREF  -  [unnamed]  212.94 42.09 0 top
NOREF#2  -  [unnamed]  76.19 138.51 0 top
NOREF#3  -  [#2]  92.06 18.37 0 top
NOREF#4  -  [#2]  119.11 -16.56 0 top
NOREF#5  -  [#2]  68.31 -57.2 0 top
NOREF#6  -  [#2]  169.23 16.11 0 top
NOREF#7  -  [unnamed]  17.36 7.04 0 top
NOREF#8  -  [unnamed]  212.94 42.09 180 bottom
NOREF#9  -  [unnamed]  17.26 7.07 180 bottom
NOREF#10  -  [#2]  5.96 14.43 180 bottom
NOREF#11  -  [unnamed]  61.33 138.64 180 bottom
NOREF#12  -  [#2]  92.85 18.49 180 bottom
PC1  1000p/50V_4  [C0402]  98.79 132.8 180 top
PC2  *0.1u/16V_4  [C0402]  131.56 132.29 180 top
PC3  *0.01u/50V_4  [C0402]  112.84 130.65 270 top
PC4  *0.01u/50V_4  [C0402]  113.96 130.65 270 top
PC5  *0.01u/50V_4  [C0402]  115.04 130.65 90 top
PC6  0.1u/25V_4  [C0402]  117.46 130.65 90 top
PC7  VL@0.1u/16V_4  [C0402]  52.58 129.78 90 top
PC8  VL@820p/50V_4  [C0402]  56.8 129.77 270 top
PC9  330p/50V_4  [C0402]  111.82 128.61 270 top
PC10  68p/50V_4  [C0402]  112.84 128.61 90 top
PC11  0.01u/50V_4  [C0402]  116.42 128.61 90 top
PC12  0.022u/50V_4  [C0402]  107.54 127.08 180 top
PC13  *680p/50V_6  [C0603]  128.97 127.36 270 top
PC14  1000p/50V_4  [C0402]  74.32 125.94 90 top
PC15  1000p/50V_4  [C0402]  107.68 124.54 0 top
PC16  VL@0.1u/25V_4  [C0402]  57.3 125.16 0 top
PC17  0.01u/50V_4  [C0402]  104.38 123.53 180 top
PC18  68p/50V_4  [C0402]  109.59 123.4 180 top
PC19  *0.01u/50V_4  [C0402]  106.16 123.02 90 top
PC20  *330u/2V_7343H1.9  [CC7343]  100.72 123.68 90 top
PC21  *22u/6.3V_8  [C0805]  88.51 123.53 0 top
PC22  22u/6.3V_8  [C0805]  88.51 121.49 0 top
PC23  22u/6.3V_8  [C0805]  82.54 121.39 180 top
PC24  22u/6.3V_8  [C0805]  104.13 120.27 270 top
PC25  *22u/6.3V_8  [C0805]  88.51 119.33 0 top
PC26  22u/6.3V_8  [C0805]  82.54 119.33 180 top
PC27  VL@10u/25V_8  [C0805]  55.23 116.67 90 top
PC28  VL@10u/25V_8  [C0805]  58.53 119.72 180 top
PC29  VL@1u/6.3V_4  [C0402]  53.5 117.3 90 top
PC30  0.1u/16V_4  [C0402]  88.63 116.03 0 top
PC31  *2200p/50V_4  [C0402]  137.53 92.29 270 top
PC32  *0.1u/16V_4  [C0402]  145.53 82.63 180 top
PC33  *680p/50V_6  [C0603]  137.81 82.35 0 top
PC34  470p/50V_4  [C0402]  145.53 81.49 0 top
PC35  10u/6.3V_6  [C0603]  42.79 74.63 90 top
PC36  *10u/6.3V_6  [C0603]  44.31 74.63 90 top
PC37  0.1u/50V_6  [C0603]  230.49 44.66 90 top
PC38  2200p/50V_6  [C0603]  232.14 44.66 90 top
PC39  0.1u/16V_4  [C0402]  103.36 32.85 0 top
PC40  *680p/50V_6  [C0603]  89.42 28.63 270 top
PC41  *0.1u/16V_4  [C0402]  107.43 28.28 180 top
PC42  0.1u/25V_4  [C0402]  39 27.93 0 top
PC43  *100p/50V_4  [C0402]  63.74 27.59 180 top
PC44  2200p/50V_4  [C0402]  63.8 26.17 180 top
PC45  0.1u/50V_6  [C0603]  45.88 25.57 270 top
PC46  0.1u/50V_6  [C0603]  44.22 25.56 90 top
PC47  *0.1u/16V_4  [C0402]  107.37 25.35 90 top
PC48  2200p/50V_4  [C0402]  55.23 25.23 0 top
PC49  2200p/50V_4  [C0402]  55.23 23.7 0 top
PC50  0.1u/50V_6  [C0603]  45.04 23.46 180 top
PC51  0.47u/25V_6  [C0603]  48.03 22.29 0 top
PC52  *680p/50V_6  [C0603]  57.23 21.35 270 top
PC53  100p/50V_4  [C0402]  39.64 21.11 180 top
PC54  0.047u/50V_6  [C0603]  48.03 20.76 180 top
PC55  0.1u/50V_6  [C0603]  36.04 19.72 270 top
PC56  *47p/50V_4  [C0402]  76.06 19.13 270 top
PC57  *47p/50V_4  [C0402]  77.96 19.13 270 top
PC58  0.01u/50V_4  [C0402]  39.54 18.07 180 top
PC59  1u/16V_6  [C0603]  46.03 16.94 90 top
PC60  0.1u/25V_4  [C0402]  42.7 15.38 180 top
PC61  0.1u/25V_4  [C0402]  43.7 14.2 0 top
PC62  0.1u/25V_4  [C0402]  41.69 14.16 180 top
PC63  0.1u/25V_4  [C0402]  124.07 139.02 0 bottom
PC64  10u/25V_8  [C0805]  126.73 138.26 180 bottom
PC65  2200p/50V_4  [C0402]  124.07 138 0 bottom
PC66  4.7u/10V_6  [C0603]  82.28 137.01 0 bottom
PC67  4.7u/6.3V_4  [C0402_2]  99.25 136.71 0 bottom
PC68  0.1u/25V_4  [C0402]  124.07 136.99 0 bottom
PC69  10u/25V_8  [C0805]  126.73 136.23 180 bottom
PC70  10u/25V_8  [C0805]  86.88 135.64 90 bottom
PC71  10u/25V_8  [C0805]  88.94 135.64 90 bottom
PC72  2200p/50V_4  [C0402]  85.41 135.56 270 bottom
PC73  0.1u/50V_6  [C0603]  90.64 135.41 270 bottom
PC74  2200p/50V_4  [C0402]  74.79 135.11 270 bottom
PC75  0.1u/50V_6  [C0603]  92.67 134.7 180 bottom
PC76  0.1u/50V_6  [C0603]  73.47 134.68 270 bottom
PC77  10u/25V_8  [C0805]  69.61 134.37 90 bottom
PC78  10u/25V_8  [C0805]  71.64 134.37 90 bottom
PC79  0.1u/50V_6  [C0603]  79.49 134.07 180 bottom
PC80  *33u/25V_D6.3H4.5  [ECAP6_3X6_1-7_2]  105.9 132.54 0 bottom
PC81  8200p/50V_4  [C0402]  112.84 130.65 270 bottom
PC82  *680p/50V_4  [C0402]  113.96 130.65 270 bottom
PC83  2200p/50V_4  [C0402]  115.04 130.65 270 bottom
PC84  470p/50V_4  [C0402]  131.56 131.27 0 bottom
PC85  4.7u/6.3V_4  [C0402_2]  131.18 129.42 180 bottom
PC86  0.047u/16V_4  [C0402]  116.42 128.61 270 bottom
PC87  2200p/50V_4  [C0402]  117.46 128.61 90 bottom
PC88  0.1u/25V_4  [C0402]  122.41 127.46 0 bottom
PC89  0.1u/25V_4  [C0402]  107.54 127.08 0 bottom
PC90  0.1u/25V_4  [C0402]  105.76 126.33 90 bottom
PC91  2200p/50V_4  [C0402]  109.59 125.94 180 bottom
PC92  1u/25V_4  [C0402]  118.86 125.18 180 bottom
PC93  0.1u/16V_4  [C0402]  72.88 125.43 0 bottom
PC94  1200p/50V_4  [C0402]  107.68 124.54 0 bottom
PC95  1u/25V_4  [C0402]  118.86 124.03 180 bottom
PC96  8200p/50V_4  [C0402]  107.68 123.4 0 bottom
PC97  22u/6.3V_8  [C0805]  72.25 123.78 0 bottom
PC98  *0.01u/50V_4  [C0402]  106.16 123.02 270 bottom
PC99  22u/6.3V_8  [C0805]  88.51 123.53 0 bottom
PC100  330p/50V_4  [C0402]  109.59 122.26 0 bottom
PC101  22u/6.3V_8  [C0805]  72.25 121.81 0 bottom
PC102  0.1u/16V_4  [C0402]  131.18 121.62 180 bottom
PC103  22u/6.3V_8  [C0805]  88.51 121.49 0 bottom
PC104  22u/6.3V_8  [C0805]  82.54 121.37 180 bottom
PC105  22u/6.3V_8  [C0805]  104.13 120.27 270 bottom
PC106  22u/6.3V_8  [C0805]  72.25 119.84 0 bottom
PC107  *22u/6.3V_8  [C0805]  130.67 119.72 180 bottom
PC108  22u/6.3V_8  [C0805]  107.56 119.46 180 bottom
PC109  22u/6.3V_8  [C0805]  88.51 119.33 0 bottom
PC110  22u/6.3V_8  [C0805]  82.54 119.21 180 bottom
PC111  10u/6.3V_6  [C0603]  116.32 118.32 180 bottom
PC112  *22u/6.3V_8  [C0805]  130.67 117.68 180 bottom
PC113  *22u/6.3V_8  [C0805]  88.51 117.36 0 bottom
PC114  22u/6.3V_8  [C0805]  107.56 117.3 180 bottom
PC115  0.1u/16V_4  [C0402]  116.28 117.02 180 bottom
PC116  1u/25V_4  [C0402]  118.1 117.02 0 bottom
PC117  *0.1u/16V_4  [C0402]  121.27 115.5 180 bottom
PC118  22u/6.3V_8  [C0805]  107.56 115.33 180 bottom
PC119  1000p/50V_4  [C0402]  113.52 115.02 0 bottom
PC120  0.1u/16V_4  [C0402]  121.27 114.43 180 bottom
PC121  22u/6.3V_8  [C0805]  125.59 114.13 90 bottom
PC122  22u/6.3V_8  [C0805]  127.75 114.13 90 bottom
PC123  22u/6.3V_8  [C0805]  129.91 114.13 90 bottom
PC124  1000p/50V_4  [C0402]  113.52 113.87 0 bottom
PC125  *0.1u/16V_4  [C0402]  121.27 113.37 180 bottom
PC126  22u/6.3V_8  [C0805]  107.56 113.36 180 bottom
PC127  *VL@22u/25V_8  [C0805]  48.25 107.02 180 bottom
PC128  22u/6.3V_8  [C0805]  91.81 112.48 90 bottom
PC129  22u/6.3V_8  [C0805]  93.97 112.48 90 bottom
PC130  22u/6.3V_8  [C0805]  96.13 112.48 90 bottom
PC131  22u/6.3V_8  [C0805]  98.28 112.48 90 bottom
PC132  22u/6.3V_8  [C0805]  100.44 112.48 90 bottom
PC133  22u/6.3V_8  [C0805]  102.6 112.48 90 bottom
PC134  22u/6.3V_8  [C0805]  104.76 112.48 90 bottom
PC135  0.1u/16V_4  [C0402]  116.32 111.94 180 bottom
PC136  1u/25V_4  [C0402]  118.1 111.94 0 bottom
PC137  *22p/50V_4  [C0402]  128.89 111.13 90 bottom
PC138  *VL@22u/25V_8  [C0805]  48.25 104.98 180 bottom
PC139  10u/6.3V_6  [C0603]  116.32 110.57 180 bottom
PC140  *0.1u/16V_4  [C0402]  126.61 109.73 180 bottom
PC141  *68p/50V_4  [C0402]  131.18 108.92 180 bottom
PC142  1u/6.3V_4  [C0402]  131.18 107.9 180 bottom
PC143  22u/6.3V_6  [C0603]  115.81 107.02 0 bottom
PC144  0.01u/50V_4  [C0402]  132.02 106.43 270 bottom
PC145  VL@22u/25V_8  [C0805]  51.55 107.02 0 bottom
PC146  VL@22u/25V_8  [C0805]  51.55 104.98 0 bottom
PC147  0.1u/25V_4  [C0402]  115.38 105.64 0 bottom
PC148  *2200p/50V_4  [C0402]  127.47 104.07 270 bottom
PC149  10u/6.3V_6  [C0603]  129.53 103.84 0 bottom
PC150  4.7u/6.3V_4  [C0402_2]  128.64 89.62 90 bottom
PC151  0.1u/25V_4  [C0402]  137.78 88.47 0 bottom
PC152  10u/25V_8  [C0805]  141.29 87.66 180 bottom
PC153  *10u/6.3V_6  [C0603]  128 87.46 180 bottom
PC154  0.1u/25V_4  [C0402]  137.78 87.33 0 bottom
PC155  2200p/50V_4  [C0402]  137.78 86.19 0 bottom
PC156  10u/6.3V_6  [C0603]  128 85.93 180 bottom
PC157  10u/25V_8  [C0805]  141.29 85.65 180 bottom
PC158  *0.1u/16V_4  [C0402]  133.46 85.04 270 bottom
PC159  0.1u/16V_4  [C0402]  128.51 84.66 180 bottom
PC160  0.1u/16V_4  [C0402]  116.87 84.22 90 bottom
PC161  4.7u/6.3V_4  [C0402_2]  45.7 82.58 270 bottom
PC162  4.7u/6.3V_4  [C0402_2]  145.25 79.43 90 bottom
PC163  2.2u/10V_4  [C0402]  143.65 79.02 0 bottom
PC164  0.1u/25V_4  [C0402]  139.05 78.69 0 bottom
PC165  *33u/25V_D6.3H4.5  [ECAP6_3X6_1-7_2]  132.7 77.55 0 bottom
PC166  0.1u/16V_4  [C0402]  44.94 73.36 90 bottom
PC167  0.1u/16V_4  [C0402]  50.28 75.01 90 bottom
PC168  22u/6.3V_8  [C0805]  136.64 73.61 0 bottom
PC169  22u/6.3V_8  [C0805]  136.51 71.46 0 bottom
PC170  22u/6.3V_8  [C0805]  136.51 69.3 0 bottom
PC171  0.1u/16V_4  [C0402]  145.15 68.41 180 bottom
PC172  *22u/6.3V_8  [C0805]  136.51 67.26 0 bottom
PC173  *22u/6.3V_8  [C0805]  136.51 65.23 0 bottom
PC174  0.1u/16V_4  [C0402]  145.4 59.9 270 bottom
PC175  *0.1u/16V_4  [C0402]  146.42 59.9 270 bottom
PC176  *0.1u/16V_4  [C0402]  144.39 59.87 270 bottom
PC177  1u/25V_4  [C0402]  142.65 56.98 90 bottom
PC178  1u/25V_4  [C0402]  147.77 56.85 90 bottom
PC179  10u/6.3V_6  [C0603]  141.46 55.5 270 bottom
PC180  10u/6.3V_6  [C0603]  148.96 55.48 270 bottom
PC181  0.1u/16V_4  [C0402]  142.65 55.07 270 bottom
PC182  0.1u/16V_4  [C0402]  147.77 55.07 270 bottom
PC183  1000p/50V_4  [C0402]  144.84 52.41 90 bottom
PC184  1000p/50V_4  [C0402]  145.8 52.41 90 bottom
PC185  1u/25V_4  [C0402]  137.92 50.16 180 bottom
PC186  10u/6.3V_6  [C0603]  144.51 48.47 270 bottom
PC187  10u/6.3V_6  [C0603]  134.03 48.39 270 bottom
PC188  0.1u/50V_6  [C0603]  132.01 47.76 0 bottom
PC189  *0.1u/50V_6  [C0603]  132.82 45.71 90 bottom
PC190  0.1u/50V_6  [C0603]  198.71 38.8 90 bottom
PC191  2200p/50V_4  [C0402]  96.61 35.91 180 bottom
PC192  0.1u/25V_4  [C0402]  96.6 34.77 180 bottom
PC193  10u/25V_8  [C0805]  97.29 33.17 180 bottom
PC194  22u/6.3V_8  [C0805]  83.3 31.96 270 bottom
PC195  0.033u/16V_4  [C0402]  103.75 31.3 270 bottom
PC196  10u/25V_8  [C0805]  97.29 31.14 180 bottom
PC197  10u/6.3V_6  [C0603]  101.13 31.04 0 bottom
PC198  22u/6.3V_8  [C0805]  80.5 30.69 0 bottom
PC199  0.1u/25V_4  [C0402]  90.37 30.67 0 bottom
PC200  0.1u/50V_6  [C0603]  64.53 23.93 0 top
PC201  10u/25V_8  [C0805]  62.72 27.13 90 bottom
PC202  *10u/6.3V_6  [C0603]  99.15 28.57 0 bottom
PC203  22u/6.3V_8  [C0805]  80.5 28.53 0 bottom
PC204  10u/25V_8  [C0805]  64.76 27.13 90 bottom
PC205  22u/6.3V_8  [C0805]  80.5 26.36 0 bottom
PC206  0.1u/50V_6  [C0603]  55.23 27.26 180 bottom
PC207  0.1u/50V_6  [C0603]  99.14 25.65 0 bottom
PC208  0.1u/16V_4  [C0402]  82.75 24.57 90 bottom
PC209  10u/25V_8  [C0805]  55.23 25.57 180 bottom
PC210  1u/6.3V_4  [C0402]  104.51 24.08 90 bottom
PC211  *22u/6.3V_8  [C0805]  87.13 20.29 90 bottom
PC212  *22u/6.3V_8  [C0805]  89.16 20.28 90 bottom
PC213  *10u/25V_8  [C0805]  60.06 28.66 0 bottom
PC214  *10u/25V_8  [C0805]  60.06 30.69 0 bottom
PC216  *VL@0.1u/25V_4  [C0402]  56.88 114.25 0 top
PD1  VL@DFLS240-7  [D-2_8X1_78]  51.04 115.27 90 top
PD2  P4SMAFJ20A  [D-3_8X2_5]  227.57 41.86 90 top
PD3  SV1040  [D-TO277_213-6_1X4_3]  224.55 32.62 90 top
PD4  1N4148WS  [DSM]  35.96 22.26 180 top
PD5  PDZ5.6B  [DSM]  75.55 15.45 270 top
PD6  PDZ5.6B  [DSM]  78.47 15.45 270 top
PD7  RB500V-40  [DSM]  47.51 17.54 180 bottom
PJ1  EJ@CI2504P1H02-RB-NH  [50320-0040N-001-4P-L-SMT]  226.75 42.7 270 bottom
PJ2  CB@50278-006T1-001  [50278-006T1-001-6P-L]  231.07 42.35 270 bottom
PJ5  50458-00801-V02  [50458-00801-V02-8P-L]  74.59 17.03 180 bottom
PL1  VL@3.3uH_5x5x1.8  [L5_1X5_2-1_6H]  53.57 121.15 180 top
PL2  0.47uH_7x7x3  [CHOKE-PCMC063T-3R3MN-SMT]  77.33 124.92 270 bottom
PL3  2.2uH_7x7x3  [CHOKE-PCMC063T-3R3MN-SMT]  126.83 124.87 270 bottom
PL4  0.15uH_7x7x4  [L6_6X6_6-3_8]  94.6 123.65 270 bottom
PL5  1uH_7x7x3  [CHOKE-PCMC063T-3R3MN-SMT]  120.89 104.09 180 bottom
PL6  2.2uH_2.5x2.0x1.2  [L2_5X2-1_2H]  129.02 82.63 180 bottom
PL7  2.2uH_2.5x2.0x1.2  [L2_5X2-1_2H]  46.82 74.73 270 bottom
PL8  1.5uH_7x7x3  [CHOKE-PCMC063T-3R3MN-SMT]  142.1 73.87 270 bottom
PL9  1uH_7x7x3  [CHOKE-PCMC063T-3R3MN-SMT]  88.89 25.86 180 bottom
PL10  6.8uH_7x7x3  [CHOKE-PCMC063T-3R3MN-SMT]  56.79 20.08 270 bottom
PQ1  2N7002K  [SOT23_213-3_3-2]  140.19 91.9 0 top
PQ2  DDTC144EUA-7-F  [UMT_213-3-1_3]  144.64 91.78 0 top
PQ3  2N7002K  [SOT23_213-3_3-2]  44.51 89.11 90 top
